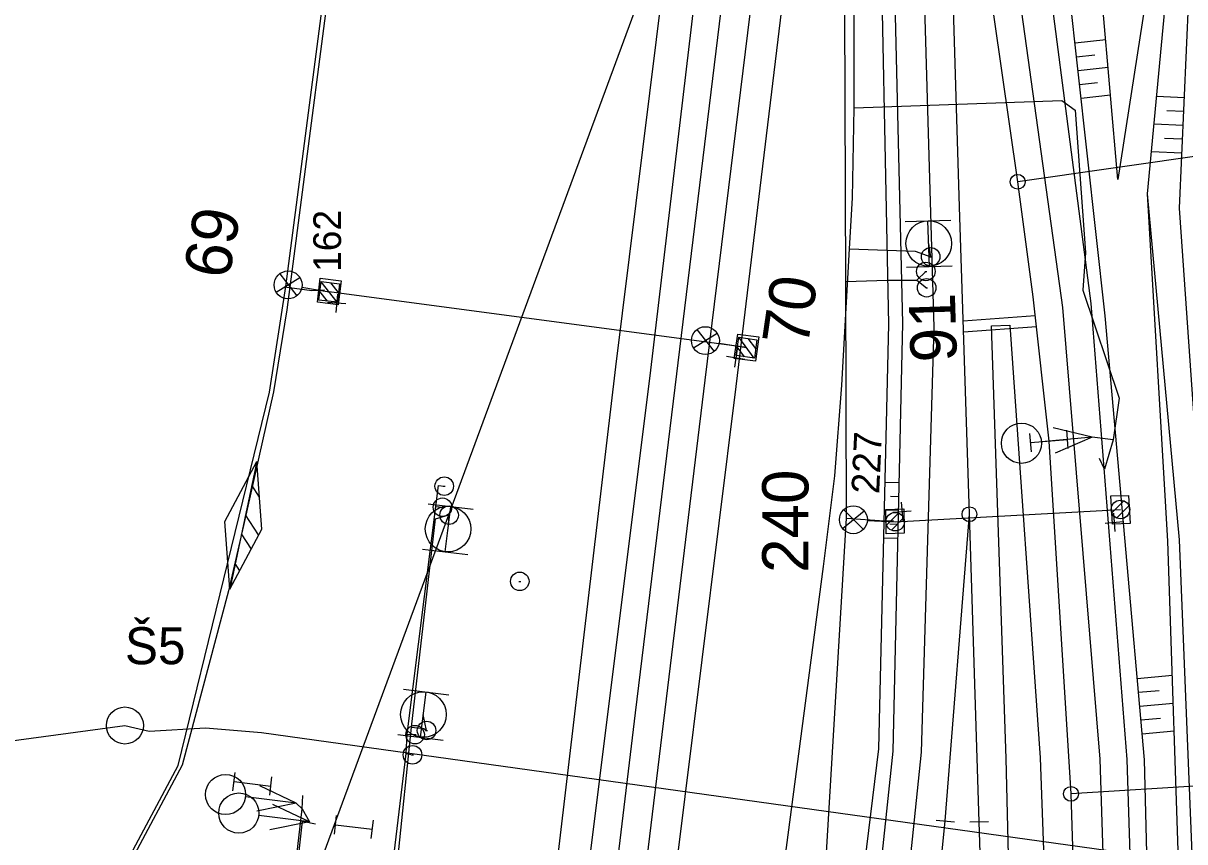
# Model space of a CAD drawing. Extents: x -598638 to -597933, y -1164002 to -1161904.
# Drawn here: x -598553.5 to -598490.7, y -1163455.2 to -1163411 of the extents above; entities that cross this region are included whole.
import ezdxf

# ---------------------------------------------------------------- set-up
doc = ezdxf.new("R2010")
doc.units = 0
for name, color, linetype in [('Vrstva 1', 7, 'Continuous'), ('Vrstva 11', 7, 'Continuous'), ('Vrstva 12', 7, 'Continuous'), ('Vrstva 13', 7, 'Continuous'), ('Vrstva 2', 7, 'Continuous'), ('Vrstva 25', 7, 'Continuous'), ('Vrstva 26', 7, 'Continuous'), ('Vrstva 28', 7, 'Continuous'), ('Vrstva 3', 7, 'Continuous'), ('Vrstva 31', 7, 'Continuous'), ('Vrstva 35', 7, 'Continuous'), ('Vrstva 4', 7, 'Continuous'), ('Vrstva 43', 7, 'Continuous'), ('Vrstva 44', 7, 'Continuous'), ('Vrstva 48', 7, 'Continuous'), ('Vrstva 49', 7, 'Continuous'), ('Vrstva 51', 7, 'Continuous'), ('Vrstva 63', 7, 'Continuous'), ('Vrstva 7', 7, 'Continuous')]:
    doc.layers.add(name, color=color, linetype=linetype)

msp = doc.modelspace()

# ---------------------------------------------------------------- linework, layer by layer
at = {"layer": 'Vrstva 1'}
for p, q in [((-598440.373, -1163411.059), (-598499.762, -1163419.602)), ((-598436.998, -1163448.911), (-598496.881, -1163452.657))]:
    msp.add_line(p, q, dxfattribs=at)
for points in [[(-598540.061, -1163609.51), (-598538.55, -1163597.18), (-598535.661, -1163573.393), (-598532.502, -1163547.551), (-598529.47, -1163522.734), (-598526.451, -1163497.915), (-598523.419, -1163473.102), (-598521.347, -1163456.074), (-598520.4, -1163448.28), (-598517.374, -1163423.469), (-598514.348, -1163398.653), (-598511.323, -1163373.834), (-598509.75, -1163360.838), (-598508.294, -1163349.021), (-598507.057, -1163338.802)], [(-598499.762, -1163419.602), (-598501.472, -1163407.683)], [(-598502.896, -1163420.949), (-598503.303, -1163407.847)], [(-598496.881, -1163452.657), (-598498.066, -1163433.602), (-598498.934, -1163425.811), (-598499.762, -1163419.602)], [(-598501.838, -1163454.16), (-598502.367, -1163437.555), (-598502.896, -1163420.949)], [(-598503.675, -1163454.123), (-598502.367, -1163437.555)], [(-598496.171, -1163474.917), (-598496.881, -1163452.657)], [(-598504.943, -1163466.8), (-598503.675, -1163454.123)], [(-598501.424, -1163467.022), (-598501.838, -1163454.16)]]:
    msp.add_lwpolyline(points, dxfattribs=at)
for centre in [(-598499.762, -1163419.602), (-598496.881, -1163452.657)]:
    msp.add_circle(centre, 0.4, dxfattribs=at)
at = {"layer": 'Vrstva 11'}
for p, q in [((-598536.514, -1163426.104), (-598537.39, -1163424.999)), ((-598536.45, -1163425.58), (-598536.866, -1163425.056)), ((-598537.04, -1163426.043), (-598537.45, -1163425.525)), ((-598514.514, -1163429.05), (-598514.91, -1163428.521)), ((-598513.989, -1163429.126), (-598514.834, -1163427.997)), ((-598513.911, -1163428.605), (-598514.312, -1163428.069)), ((-598494.671, -1163437.484), (-598494.025, -1163436.838)), ((-598494.411, -1163437.754), (-598493.756, -1163437.099)), ((-598506.841, -1163438.144), (-598506.195, -1163437.498)), ((-598506.581, -1163438.414), (-598505.926, -1163437.759))]:
    msp.add_line(p, q, dxfattribs=at)
for points in [[(-598537.504, -1163425.989), (-598537.389, -1163424.996), (-598536.396, -1163425.111), (-598536.511, -1163426.104)], [(-598514.976, -1163428.984), (-598514.834, -1163427.994), (-598513.844, -1163428.136), (-598513.986, -1163429.126)]]:
    msp.add_lwpolyline(points, close=True, dxfattribs=at)
for points in [[(-598537.504, -1163425.989), (-598537.389, -1163424.996), (-598536.396, -1163425.111), (-598536.511, -1163426.104), (-598537.504, -1163425.989)], [(-598514.41, -1163428.56), (-598536.95, -1163425.55)], [(-598514.976, -1163428.984), (-598514.834, -1163427.994), (-598513.844, -1163428.136), (-598513.986, -1163429.126), (-598514.976, -1163428.984)], [(-598506.38, -1163437.96), (-598494.21, -1163437.3)]]:
    msp.add_lwpolyline(points, dxfattribs=at)
for centre in [(-598494.21, -1163437.3), (-598506.38, -1163437.96)]:
    msp.add_circle(centre, 0.5, dxfattribs=at)
at = {"layer": 'Vrstva 12'}
for points in [[(-598536.3, -1163424.96), (-598536.46, -1163426.25), (-598537.59, -1163426.11), (-598537.44, -1163424.81), (-598536.3, -1163424.96)], [(-598515.07, -1163429.15), (-598514.88, -1163427.83), (-598513.74, -1163427.97), (-598513.92, -1163429.29), (-598515.07, -1163429.15)], [(-598494.64, -1163438.09), (-598494.73, -1163436.56), (-598493.77, -1163436.55), (-598493.69, -1163438.05), (-598494.64, -1163438.09)], [(-598505.91, -1163437.27), (-598505.89, -1163438.58), (-598506.87, -1163438.62), (-598506.88, -1163437.3), (-598505.91, -1163437.27)]]:
    msp.add_lwpolyline(points, dxfattribs=at)
at = {"layer": 'Vrstva 13'}
for points in [[(-598494.35, -1163419.483), (-598496.011, -1163400.454), (-598498.249, -1163378.174), (-598498.761, -1163353.124), (-598499.609, -1163337.312), (-598498.929, -1163312.944), (-598495.877, -1163288.306), (-598493.588, -1163272.056)], [(-598496.865, -1163550.379), (-598493.505, -1163528.163), (-598490.621, -1163501.64), (-598489.924, -1163482.727), (-598490.976, -1163458.949), (-598491.652, -1163439.005), (-598492.756, -1163420.248), (-598491.376, -1163405.706)], [(-598496.865, -1163550.379), (-598496.294, -1163550.405), (-598492.926, -1163528.273), (-598489.969, -1163501.763), (-598489.191, -1163482.813), (-598490.216, -1163459.012), (-598491.02, -1163438.946), (-598492.756, -1163420.248)]]:
    msp.add_lwpolyline(points, dxfattribs=at)
at = {"layer": 'Vrstva 2'}
for p, q in [((-598504.174, -1163454.084), (-598503.177, -1163454.163)), ((-598502.338, -1163454.176), (-598501.338, -1163454.144))]:
    msp.add_line(p, q, dxfattribs=at)
for points in [[(-598501.838, -1163454.16), (-598502.367, -1163437.555), (-598502.896, -1163420.949)], [(-598503.675, -1163454.123), (-598502.367, -1163437.555)]]:
    msp.add_lwpolyline(points, dxfattribs=at)
msp.add_circle((-598502.366, -1163437.556), 0.4, dxfattribs=at)
at = {"layer": 'Vrstva 25'}
for p, q in [((-598504.51, -1163423.65), (-598504.41, -1163423.65)), ((-598539.627, -1163424.57), (-598538.705, -1163425.764)), ((-598504.775, -1163424.444), (-598504.675, -1163424.444)), ((-598539.812, -1163425.568), (-598538.535, -1163424.768)), ((-598538.429, -1163425.299), (-598536.95, -1163425.55)), ((-598504.729, -1163425.327), (-598504.629, -1163425.327)), ((-598517.272, -1163428.578), (-598515.995, -1163427.778)), ((-598517.087, -1163427.58), (-598516.165, -1163428.774)), ((-598515.889, -1163428.309), (-598514.41, -1163428.56)), ((-598530.788, -1163436.041), (-598530.688, -1163436.041)), ((-598530.884, -1163437.179), (-598530.784, -1163437.179)), ((-598509.155, -1163437.31), (-598508.097, -1163438.384)), ((-598530.54, -1163437.59), (-598530.44, -1163437.59)), ((-598509.219, -1163438.323), (-598508.047, -1163437.375)), ((-598507.878, -1163437.889), (-598506.38, -1163437.96)), ((-598532.362, -1163449.461), (-598532.262, -1163449.461)), ((-598531.75, -1163449.24), (-598531.65, -1163449.24)), ((-598532.503, -1163450.55), (-598532.403, -1163450.55))]:
    msp.add_line(p, q, dxfattribs=at)
for centre, radius in [((-598504.463, -1163423.652), 0.5), ((-598504.725, -1163424.444), 0.5), ((-598539.172, -1163425.171), 0.754), ((-598504.679, -1163425.327), 0.5), ((-598516.632, -1163428.181), 0.754), ((-598530.738, -1163436.041), 0.5), ((-598530.834, -1163437.179), 0.5), ((-598530.476, -1163437.605), 0.5), ((-598508.636, -1163437.852), 0.754), ((-598532.312, -1163449.461), 0.5), ((-598531.695, -1163449.237), 0.5), ((-598532.453, -1163450.55), 0.5)]:
    msp.add_circle(centre, radius, dxfattribs=at)
at = {"layer": 'Vrstva 26'}
for points in [[(-598545.332, -1163489.631), (-598545.008, -1163488.013), (-598544.032, -1163482.82), (-598544.736, -1163479.954), (-598543.755, -1163474.998), (-598543.294, -1163474.254), (-598542.12, -1163472.372), (-598541.435, -1163468.483), (-598542.191, -1163467.82), (-598543.3, -1163466.865), (-598549.702, -1163463.438), (-598550.312, -1163461.998), (-598547.972, -1163456.485), (-598545.109, -1163451.121), (-598540.175, -1163430.965), (-598539.287, -1163425.257), (-598536.381, -1163402.898), (-598536.647, -1163397.91), (-598537.412, -1163388.462)], [(-598509.054, -1163424.983), (-598509.135, -1163400.512), (-598511.269, -1163400.35), (-598532.35, -1163398.602), (-598532.805, -1163398.581), (-598536.647, -1163397.91)], [(-598509.054, -1163424.983), (-598506.814, -1163424.919), (-598505.218, -1163424.908), (-598504.725, -1163424.444)], [(-598539.366, -1163425.268), (-598537.883, -1163425.477), (-598537.208, -1163425.444)], [(-598516.596, -1163487.785), (-598514.603, -1163479.279), (-598512.946, -1163472.722), (-598510.637, -1163464.87), (-598509.011, -1163437.76), (-598509.054, -1163424.983)], [(-598505.218, -1163424.908), (-598504.679, -1163425.327)], [(-598543.294, -1163474.254), (-598540.098, -1163474.897), (-598535.703, -1163475.505), (-598535.584, -1163473.956), (-598533.441, -1163455.87), (-598532.804, -1163450.473), (-598532.749, -1163449.438), (-598531.188, -1163437.14), (-598531.046, -1163436.005), (-598530.738, -1163436.041)], [(-598531.188, -1163437.14), (-598530.834, -1163437.179)], [(-598509.011, -1163437.76), (-598506.976, -1163437.919), (-598506.476, -1163437.886)], [(-598532.749, -1163449.438), (-598532.312, -1163449.461)], [(-598532.804, -1163450.473), (-598532.453, -1163450.55)], [(-598551.86, -1163490.896), (-598550.979, -1163486.167), (-598545.539, -1163476.175), (-598540.296, -1163462.996), (-598539.364, -1163462.898), (-598538.397, -1163454.139), (-598537.686, -1163454.273)]]:
    msp.add_lwpolyline(points, dxfattribs=at)
at = {"layer": 'Vrstva 28'}
for points in [[(-598514.7, -1163462.74), (-598512.83, -1163458.19), (-598512.34, -1163456.24), (-598510.26, -1163440.38), (-598509.64, -1163435.49), (-598509.26, -1163430.59), (-598508.84, -1163423.22), (-598508.68, -1163420.47), (-598508.59, -1163415.6), (-598508.57, -1163404.31), (-598508.02, -1163387.15), (-598507.28, -1163376.57), (-598507.52, -1163372.71), (-598507.43, -1163364.54), (-598507.33, -1163362.84), (-598506.87, -1163362.23), (-598507.2, -1163361.02)], [(-598536.213, -1163400.645), (-598536.168, -1163402.882), (-598539.241, -1163426.522), (-598539.962, -1163430.949), (-598541.59, -1163438.158), (-598542.388, -1163441.691), (-598544.896, -1163451.105), (-598547.759, -1163456.469), (-598550.099, -1163461.982), (-598549.524, -1163463.34), (-598543.087, -1163466.786), (-598541.213, -1163468.412), (-598540.83, -1163467.6), (-598540.45, -1163467.34), (-598539.56, -1163463.45), (-598538.42, -1163453.46), (-598538.38, -1163452.75)], [(-598508.59, -1163415.6), (-598497.37, -1163415.22), (-598496.66, -1163415.74), (-598496.1, -1163423.42), (-598496.25, -1163425.46), (-598494.28, -1163431.28), (-598494.6, -1163433.53), (-598495.07, -1163435.12), (-598495.35, -1163434.54)], [(-598508.84, -1163423.22), (-598505.3, -1163423.35), (-598504.46, -1163423.65), (-598504.57, -1163422.94)], [(-598494.6, -1163433.53), (-598495.73, -1163433.4)], [(-598541.213, -1163468.412), (-598541.912, -1163472.382), (-598541.94, -1163474.57), (-598540.43, -1163474.83), (-598535.85, -1163475.55), (-598535.63, -1163474.75), (-598533.25, -1163456.19), (-598532.5, -1163449.06), (-598531.21, -1163437.8), (-598530.49, -1163437.59), (-598530.54, -1163438.36)], [(-598532.5, -1163449.06), (-598531.84, -1163449.12), (-598531.7, -1163449.24), (-598531.87, -1163448.38)], [(-598538.73, -1163453.16), (-598538.42, -1163453.46), (-598538.02, -1163454.16)]]:
    msp.add_lwpolyline(points, dxfattribs=at)
at = {"layer": 'Vrstva 3'}
for p, q in [((-598505.84, -1163421.747), (-598503.377, -1163421.67)), ((-598504.532, -1163424.171), (-598504.608, -1163421.709)), ((-598505.763, -1163424.21), (-598503.3, -1163424.133)), ((-598495.73, -1163433.4), (-598497.852, -1163432.891)), ((-598499.019, -1163434.187), (-598499.105, -1163433.19)), ((-598499.062, -1163433.688), (-598497.07, -1163433.516)), ((-598495.73, -1163433.4), (-598498.48, -1163433.639)), ((-598495.73, -1163433.4), (-598497.733, -1163434.266)), ((-598497.027, -1163434.014), (-598497.113, -1163433.017)), ((-598531.614, -1163436.988), (-598529.168, -1163437.286)), ((-598530.689, -1163439.583), (-598530.391, -1163437.137)), ((-598531.912, -1163439.434), (-598529.466, -1163439.732)), ((-598532.944, -1163447.008), (-598530.498, -1163447.306)), ((-598532.019, -1163449.603), (-598531.721, -1163447.157)), ((-598533.242, -1163449.454), (-598530.796, -1163449.752)), ((-598542.153, -1163452.496), (-598542.032, -1163451.503)), ((-598542.093, -1163451.999), (-598540.107, -1163452.241)), ((-598538.73, -1163453.16), (-598540.702, -1163452.226)), ((-598540.168, -1163452.737), (-598540.047, -1163451.744)), ((-598538.73, -1163453.16), (-598541.47, -1163452.827)), ((-598538.73, -1163453.16), (-598540.868, -1163453.595)), ((-598538.02, -1163454.16), (-598539.991, -1163453.225)), ((-598538.02, -1163454.16), (-598540.76, -1163453.826)), ((-598538.02, -1163454.16), (-598540.158, -1163454.595)), ((-598536.673, -1163454.826), (-598536.552, -1163453.833)), ((-598534.688, -1163455.067), (-598534.567, -1163454.074)), ((-598536.613, -1163454.329), (-598534.627, -1163454.571))]:
    msp.add_line(p, q, dxfattribs=at)
for centre, radius in [((-598504.568, -1163422.938), 1.232), ((-598499.558, -1163433.724), 1.084), ((-598530.534, -1163438.353), 1.232), ((-598531.864, -1163448.371), 1.232), ((-598542.551, -1163452.693), 1.084), ((-598541.835, -1163453.695), 1.084)]:
    msp.add_circle(centre, radius, dxfattribs=at)
at = {"layer": 'Vrstva 31'}
for p, q in [((-598540.837, -1163435.121), (-598540.922, -1163434.994)), ((-598540.71, -1163436.634), (-598541.132, -1163435.989)), ((-598540.769, -1163438.664), (-598541.47, -1163437.588)), ((-598541.155, -1163439.437), (-598541.687, -1163438.62)), ((-598541.774, -1163440.607), (-598542.025, -1163440.222)), ((-598542.187, -1163441.337), (-598542.236, -1163441.218))]:
    msp.add_line(p, q, dxfattribs=at)
for points in [[(-598537.199, -1163388.446), (-598536.213, -1163400.645), (-598536.168, -1163402.882), (-598539.241, -1163426.522), (-598539.962, -1163430.949), (-598541.59, -1163438.158), (-598542.388, -1163441.691), (-598544.896, -1163451.105), (-598547.759, -1163456.469), (-598550.099, -1163461.982), (-598549.524, -1163463.34), (-598543.087, -1163466.786), (-598541.213, -1163468.412), (-598541.912, -1163472.382), (-598543.54, -1163474.971), (-598544.53, -1163479.976), (-598543.818, -1163482.855), (-598547.027, -1163483.149)], [(-598542.318, -1163441.606), (-598542.586, -1163437.948), (-598540.862, -1163434.71)]]:
    msp.add_lwpolyline(points, dxfattribs=at)
msp.add_lwpolyline([(-598542.318, -1163441.606), (-598540.594, -1163438.368), (-598540.862, -1163434.71)], close=True, dxfattribs=at)
at = {"layer": 'Vrstva 35'}
msp.add_lwpolyline([(-598508.59, -1163415.6), (-598497.37, -1163415.22)], dxfattribs=at)
at = {"layer": 'Vrstva 4'}
msp.add_lwpolyline([(-598497.798, -1163553.336), (-598494.995, -1163527.601), (-598492.818, -1163506.812), (-598492.18, -1163480.33), (-598492.913, -1163450.825), (-598495.032, -1163426.834), (-598497.953, -1163400.465), (-598500.02, -1163378.635), (-598500.795, -1163353.032), (-598500.992, -1163338.686), (-598498.929, -1163312.944)], dxfattribs=at)
at = {"layer": 'Vrstva 43'}
msp.add_circle((-598547.987, -1163448.966), 1, dxfattribs=at)
at = {"layer": 'Vrstva 44'}
msp.add_lwpolyline([(-598568.555, -1163448.968), (-598566.897, -1163449.681), (-598563.207, -1163450.317), (-598559.469, -1163450.523), (-598547.987, -1163448.966), (-598546.677, -1163449.27), (-598543.637, -1163449.086), (-598540.603, -1163449.346), (-598478.191, -1163458.032), (-598477.405, -1163458.401), (-598470.862, -1163458.159), (-598464.548, -1163456.428), (-598412.257, -1163434.502), (-598410.629, -1163434.222), (-598407.165, -1163433.163), (-598403.637, -1163432.342), (-598346.555, -1163418.577)], dxfattribs=at)
at = {"layer": 'Vrstva 48'}
for p, q in [((-598495.008, -1163411.941), (-598496.661, -1163412.124)), ((-598495.597, -1163412.761), (-598496.579, -1163412.87)), ((-598494.878, -1163413.436), (-598496.496, -1163413.615)), ((-598495.453, -1163414.254), (-598496.414, -1163414.36)), ((-598494.747, -1163414.93), (-598496.331, -1163415.106)), ((-598492.256, -1163414.975), (-598490.755, -1163415.042)), ((-598491.711, -1163415.749), (-598490.789, -1163415.79)), ((-598492.397, -1163416.468), (-598490.823, -1163416.538)), ((-598491.823, -1163417.243), (-598490.856, -1163417.286)), ((-598492.539, -1163417.96), (-598490.89, -1163418.035)), ((-598506.921, -1163435.827), (-598506.16, -1163435.844)), ((-598506.634, -1163436.584), (-598506.177, -1163436.594)), ((-598506.957, -1163437.326), (-598506.194, -1163437.344)), ((-598506.669, -1163438.083), (-598506.211, -1163438.093)), ((-598506.992, -1163438.826), (-598506.228, -1163438.843)), ((-598491.406, -1163446.271), (-598493.3, -1163446.439)), ((-598492.122, -1163447.087), (-598493.234, -1163447.186)), ((-598491.355, -1163447.772), (-598493.168, -1163447.933)), ((-598492.039, -1163448.586), (-598493.102, -1163448.68)), ((-598491.304, -1163449.274), (-598493.036, -1163449.427))]:
    msp.add_line(p, q, dxfattribs=at)
at = {"layer": 'Vrstva 49'}
for points in [[(-598533.45, -1163670.11), (-598536.816, -1163665.931), (-598535.031, -1163653.367), (-598531.766, -1163626.047), (-598527.127, -1163591.782), (-598522.536, -1163563.12), (-598519.726, -1163549.297), (-598516.46, -1163523.044), (-598514.479, -1163505.41), (-598510.834, -1163479.337), (-598507.262, -1163450.223), (-598506.719, -1163427.295), (-598507.24, -1163401.571), (-598507.685, -1163379.523)], [(-598497.798, -1163553.336), (-598494.93, -1163550.871), (-598491.112, -1163528.455), (-598487.512, -1163502.102), (-598487.008, -1163482.722), (-598488.866, -1163459.174), (-598489.773, -1163438.794), (-598491.024, -1163421.023), (-598490.384, -1163406.778), (-598491.376, -1163405.706), (-598492.434, -1163407.048), (-598494.35, -1163419.483)]]:
    msp.add_lwpolyline(points, dxfattribs=at)
at = {"layer": 'Vrstva 51'}
for points in [[(-598501.352, -1163557.294), (-598497.322, -1163527.011), (-598495.22, -1163506.407), (-598494.37, -1163480.26), (-598495.305, -1163450.791), (-598497.315, -1163426.39), (-598500.887, -1163400.701), (-598502.656, -1163378.776), (-598503.412, -1163354.17), (-598503.666, -1163338.931), (-598502.177, -1163312.329), (-598499.265, -1163287.777)], [(-598497.685, -1163287.962), (-598500.382, -1163312.707), (-598501.939, -1163338.79), (-598501.766, -1163354.027), (-598500.944, -1163378.633), (-598499.148, -1163400.517), (-598495.815, -1163426.176), (-598493.871, -1163450.799), (-598492.924, -1163480.338), (-598493.516, -1163506.634), (-598495.537, -1163527.526), (-598499.905, -1163557.48), (-598501.352, -1163557.294)], [(-598538.768, -1163586.309), (-598539.802, -1163586.224), (-598538.809, -1163572.569), (-598537.239, -1163559.929), (-598532.111, -1163517.921), (-598526.717, -1163473.944), (-598521.465, -1163429.602), (-598514.887, -1163376.546), (-598510.204, -1163338.254)], [(-598538.768, -1163586.309), (-598535.642, -1163560.269), (-598530.513, -1163518.107), (-598525.128, -1163474.169), (-598519.579, -1163429.781), (-598513.288, -1163376.745), (-598508.587, -1163338.31)], [(-598534.658, -1163696.543), (-598531.502, -1163671.551), (-598529.287, -1163653.433), (-598525.975, -1163626.57), (-598521.938, -1163592.563), (-598518.465, -1163564.479), (-598513.549, -1163524.372), (-598511.098, -1163505.278), (-598507.979, -1163479.625), (-598504.96, -1163450.403), (-598504.276, -1163427.476), (-598505.025, -1163401.487), (-598505.825, -1163378.899), (-598506.504, -1163355.19), (-598507.471, -1163355.188), (-598510.311, -1163378.58), (-598508.823, -1163379.075)], [(-598576.024, -1163916.782), (-598567.765, -1163849.248), (-598562.666, -1163807.337), (-598557.481, -1163765.121), (-598551.011, -1163711.819), (-598545.358, -1163665.341), (-598539.95, -1163621.544), (-598532.519, -1163560.697), (-598527.374, -1163518.619), (-598522.03, -1163474.673), (-598516.65, -1163430.324), (-598510.109, -1163377.102)], [(-598574.157, -1163917.019), (-598566.089, -1163849.397), (-598561.002, -1163807.966), (-598555.82, -1163765.416), (-598552.514, -1163737.416), (-598552.899, -1163737.337), (-598549.975, -1163711.888), (-598548.115, -1163696.332), (-598547.607, -1163696.337), (-598543.685, -1163665.616), (-598538.398, -1163621.635), (-598530.925, -1163561.125), (-598525.708, -1163519.023), (-598520.47, -1163474.952), (-598514.977, -1163430.656), (-598508.517, -1163377.394)], [(-598534.658, -1163696.543), (-598536.237, -1163696.276), (-598532.874, -1163671.321), (-598530.993, -1163653.169), (-598527.57, -1163626.458), (-598523.511, -1163592.285), (-598520.081, -1163564.257), (-598518.332, -1163549.644), (-598515.065, -1163524.058), (-598512.806, -1163504.945), (-598509.548, -1163479.335), (-598506.49, -1163450.359), (-598505.964, -1163427.237), (-598506.578, -1163401.572), (-598507.29, -1163379.316), (-598507.685, -1163379.523), (-598508.823, -1163379.075)], [(-598506.681, -1163562.454), (-598502.255, -1163526.242), (-598500.466, -1163506.079), (-598499.676, -1163479.844), (-598500.384, -1163450.749), (-598501.179, -1163427.388), (-598500.18, -1163427.338), (-598498.539, -1163450.705), (-598497.484, -1163480.021), (-598498.326, -1163506.229), (-598500.451, -1163526.549), (-598504.238, -1163557.006), (-598504.733, -1163556.998), (-598505.412, -1163562.492), (-598506.681, -1163562.454)]]:
    msp.add_lwpolyline(points, dxfattribs=at)
at = {"layer": 'Vrstva 63'}
msp.add_line((-598539.744, -1163462.649), (-598508.824, -1163378.896), dxfattribs=at)
at = {"layer": 'Vrstva 7'}
for p, q in [((-598536.513, -1163425.663), (-598536.589, -1163426.661)), ((-598536.052, -1163426.2), (-598537.05, -1163426.124)), ((-598498.819, -1163426.844), (-598502.699, -1163427.122)), ((-598498.752, -1163427.441), (-598502.68, -1163427.722)), ((-598514.495, -1163429.191), (-598515.483, -1163429.035)), ((-598514.911, -1163428.619), (-598515.067, -1163429.607)), ((-598506.048, -1163436.913), (-598505.974, -1163437.911)), ((-598506.51, -1163437.449), (-598505.512, -1163437.375)), ((-598494.588, -1163437.492), (-598494.506, -1163438.488)), ((-598495.045, -1163438.031), (-598494.049, -1163437.949)), ((-598526.709, -1163441.183), (-598526.609, -1163441.183))]:
    msp.add_line(p, q, dxfattribs=at)
msp.add_circle((-598526.659, -1163441.183), 0.5, dxfattribs=at)

# ---------------------------------------------------------------- texts
at = {"layer": 'Vrstva 11'}
for s, rotation, p in [('69', 80.08332, (-598542.375, -1163424.921)), ('70', 81.72411, (-598511.105, -1163428.56)), ('240', 90, (-598511.064, -1163440.726))]:
    msp.add_text(s, height=2.5, rotation=rotation, dxfattribs=at).set_placement(p)
at = {"layer": 'Vrstva 2'}
msp.add_text('91', height=2.5, rotation=91.82459, dxfattribs=at).set_placement((-598503.038, -1163429.305))
at = {"layer": 'Vrstva 25'}
for s, rotation, p in [('162', 89.87407, (-598536.316, -1163424.47)), ('227', 87.30347, (-598507.248, -1163436.484))]:
    msp.add_text(s, height=1.5, rotation=rotation, dxfattribs=at).set_placement(p)
at = {"layer": 'Vrstva 43'}
msp.add_text('Š5', height=2, dxfattribs=at).set_placement((-598547.987, -1163445.657))

doc.saveas('drawing.dxf')
